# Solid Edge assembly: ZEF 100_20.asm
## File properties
Title: Zylinder
Author: ahadarics
Template: iso metric assembly.asm
Last saved by: ahadarics
Revision: 6
Application: Solid Edge
Username: ahadarics
Dokumentum tartalom típus: 1
Document Number: ZEF 100/20
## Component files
Kit_2.par
Profilrohr.par
Kolbenstange.par
Kit_1.par
Mutter.par
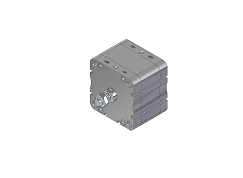
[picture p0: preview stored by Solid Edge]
